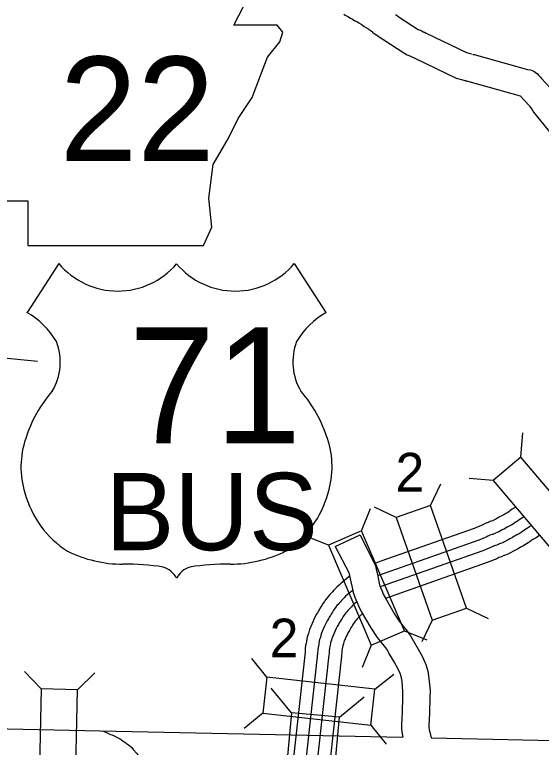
# Model space of a CAD drawing. Extents: x 535214 to 694517, y 381272 to 484355.
# Drawn here: x 541245 to 544123, y 450462 to 454464 of the extents above; entities that cross this region are included whole.
import ezdxf

# ---------------------------------------------------------------- set-up
doc = ezdxf.new("R2010")
doc.units = 0
for name, color, linetype in [('Level 10', 7, 'Continuous'), ('Level 15', 7, 'Continuous'), ('Level 19', 7, 'Continuous'), ('Level 20', 7, 'Continuous'), ('Level 21', 7, 'Continuous'), ('Level 22', 7, 'Continuous')]:
    doc.layers.add(name, color=color, linetype=linetype)

msp = doc.modelspace()

# ---------------------------------------------------------------- linework, layer by layer
at = {"layer": 'Level 10'}
for points in [[(543043.8, 454467.5), (543051.3, 454462.3), (543058.3, 454458.2), (543064.8, 454454.3), (543080.2, 454445.3), (543091.2, 454439.9), (543104.8, 454431.3), (543117.8, 454424.8), (543126.1, 454419.7), (543137.8, 454411.9), (543143.5, 454408.2), (543155, 454400.3), (543167.1, 454392.4), (543174.1, 454388.6), (543176.8, 454386.7), (543187.2, 454378.9), (543195.6, 454373.8), (543198.4, 454371.7), (543201.2, 454369.5), (543209, 454361.9), (543223.9, 454351.5), (543230.3, 454347.8), (543237, 454342.4), (543245.6, 454337.9), (543247.7, 454336.3), (543261.7, 454326.2), (543372.3, 454255.6), (543390.6, 454245.2), (543404.1, 454239.8), (543408.3, 454237.4), (543423.6, 454230.3), (543428, 454228.7), (543431.1, 454227.4), (543658.1, 454117.9), (543700.3, 454105.7), (543709.2, 454103.8)], [(543325.9, 454465.2), (543336.9, 454457), (543346.1, 454450.3), (543449.8, 454384), (543455.6, 454380.7), (543469.2, 454375.4), (543477, 454370.9), (543480.8, 454369.2), (543484.5, 454367.8), (543494.4, 454363.3), (543713.4, 454257.8), (543734.1, 454252.1), (543737.3, 454251.2), (543741.4, 454250.3)], [(543746.1, 454249.1), (543751.1, 454247.6), (543755.7, 454246.3), (544048.3, 454165.2), (544064.2, 454163.4), (544081.3, 454155), (544089.7, 454150.1), (544101.9, 454141.2), (544109.7, 454131.9), (544110.5, 454131), (544118, 454123.7), (544124.4, 454115.6), (544171.2, 454064.1), (544177.7, 454055.6), (544187.3, 454043.2), (544196.4, 454028.9), (544202.3, 454019.9), (544277.6, 453926.2), (544282.3, 453920.1), (544289.2, 453912), (544301, 453903), (544302, 453901.6), (544306.2, 453898.2), (544381.7, 453834.2)], [(543704.5, 454105), (543709.5, 454103.5), (543714.9, 454102), (544007.8, 454020.8), (544056, 453967.8), (544058.7, 453964.4), (544064.3, 453957), (544070.5, 453947.4), (544080.8, 453931.6), (544159.6, 453833.6), (544161.7, 453830.9), (544165.8, 453824.5), (544188.5, 453799.1), (544207.3, 453785.3), (544210.8, 453782.4), (544291, 453714.4)], [(542997, 451560.3), (543132.9, 451623.8)], [(543132.9, 451623.8), (543216.1, 451453.5), (543220.6, 451435.3), (543225.3, 451414.8), (543235, 451367.8), (543239.2, 451350.8), (543244.5, 451335.1), (543252.9, 451314.9), (543259.6, 451298.9), (543270.8, 451277.1), (543319.6, 451193.6), (543346.8, 451151.1), (543366.8, 451126.6), (543390.4, 451096.5), (543408.9, 451071.4), (543422.9, 451045.5), (543450.5, 450998.7), (543474.2, 450957.5), (543492.6, 450914.5), (543503.1, 450877.7), (543507.3, 450852.4), (543509.2, 450837.8), (543514.8, 450773.7), (543514.3, 450734.2), (543512.1, 450648.7), (543508.5, 450581.8), (543508.6, 450572), (543510.4, 450558.7), (543513, 450544.5), (543520.6, 450514.2)], [(542997, 451560.3), (543070.5, 451417.8), (543074.6, 451400.9), (543078.7, 451383), (543088.7, 451334.7), (543095, 451308.9), (543104, 451282.3), (543114.4, 451257.2), (543123.5, 451235.5), (543139.3, 451204.8), (543191.6, 451115.3), (543225.1, 451062.9), (543249.7, 451032.8), (543270.9, 451005.8), (543282, 450990.8), (543292.3, 450971.7), (543320.8, 450923.3), (543339.8, 450890.4), (543351, 450864.1), (543356.6, 450844.6), (543358.9, 450830.8), (543360, 450821.9), (543364.7, 450768.1), (543364.3, 450737.1), (543362.3, 450654.7), (543358.5, 450584.9), (543358.8, 450561.4), (543362.1, 450535.5), (543365.4, 450517.5)], [(541712.2, 450552.7), (543365.4, 450517.5)], [(543520.6, 450514.2), (544358, 450496.3)]]:
    msp.add_lwpolyline(points, dxfattribs=at)
at = {"layer": 'Level 15'}
for points in [[(540958.8, 454767.6), (540924.2, 453475.4), (540903.6, 452646.1), (540863.3, 450747.6), (540863.7, 450746.9), (540866.1, 450744.1), (540868.4, 450741.3), (540881.1, 450730.1), (540887.4, 450723), (540891.4, 450719.5), (540903.1, 450710), (540909.5, 450704.5), (540913.7, 450701.3), (540923.2, 450696.1), (540938.6, 450683.7), (540947.7, 450677.1), (540992.5, 450646.6), (541019.7, 450628.8), (541036.5, 450618.5), (541122.5, 450565.3), (541712.2, 450552.7)], [(541727.5, 450553.1), (541761.4, 450536.2), (541769.5, 450532.8), (541775.4, 450530.3), (541787.8, 450525.6), (541799, 450519.6), (541801.2, 450518.7), (541817.5, 450510.8), (541828, 450503.4), (541838.5, 450496.7), (541851.9, 450487), (541856.5, 450483.2), (541867.6, 450476.4), (541885, 450461.9), (541893.3, 450450.8), (541901.3, 450441.1), (541903.9, 450437.7), (541911.2, 450430.6), (541921.8, 450416.4), (541925.8, 450409.1), (541930.1, 450403), (541995.4, 450287.6)]]:
    msp.add_lwpolyline(points, dxfattribs=at)
at = {"layer": 'Level 19'}
for points in [[(543980.6, 451773), (543964.1, 451762.7), (543951.7, 451753.6), (543946.3, 451749.5), (543940.8, 451745.8), (543936.1, 451742.7), (543929.6, 451739.4), (543917.7, 451733.3), (543906, 451726.6), (543903.1, 451724.8), (543894.2, 451720.6), (543884.1, 451714), (543880.8, 451712.3), (543873.8, 451708.6), (543859.9, 451701), (543859, 451700.5), (543847.1, 451697.4), (543832.5, 451689.9), (543816.1, 451684.5), (543799.4, 451676.4), (543795.1, 451674), (543756.5, 451658.5), (543245.5, 451479), (543210.3, 451465.4)], [(544026.6, 451720.2), (544025.4, 451719.4), (544015.9, 451714), (544002.9, 451705.9), (543992.9, 451698.5), (543986.1, 451693.4), (543978.6, 451688.4), (543970.6, 451683.2), (543961.1, 451678.3), (543950.5, 451672.9), (543940.7, 451667.3), (543935.7, 451664.3), (543927.9, 451660.5), (543919.2, 451654.9), (543913.1, 451651.6), (543906.1, 451648), (543892.2, 451640.3), (543886.1, 451637.2), (543881.4, 451635.3), (543871.8, 451632.8), (543857.9, 451625.6), (543854.4, 451624.7), (543842, 451620.6), (543831, 451615.3), (543824.5, 451611.7), (543780.7, 451594.2), (543228.3, 451400)], [(544064, 451670.1), (544058.2, 451666.2), (544047.9, 451660.3), (544038.1, 451654.2), (544030.3, 451648.4), (544022.2, 451642.3), (544012.9, 451636.1), (544002, 451629.1), (543989.7, 451622.7), (543980.4, 451617.9), (543972.3, 451613.3), (543965.4, 451609.2), (543958.4, 451605.8), (543951.2, 451601.2), (543942.5, 451596.4), (543935.5, 451592.8), (543921.6, 451585.1), (543911.9, 451580.1), (543900.7, 451575.8), (543894.3, 451574.1), (543880.4, 451566.9), (543872.1, 451564.7), (543865.5, 451562.6), (543859.7, 451559.7), (543851.3, 451555.1), (543802.7, 451535.6), (543242.9, 451338.9)], [(544112.2, 451619.8), (544110, 451618.1), (544094.3, 451607.6), (544083.1, 451601.3), (544076.9, 451597.4), (544071.4, 451593.3), (544062, 451586.2), (544050.6, 451578.7), (544036.6, 451569.5), (544021.2, 451561.6), (544013.2, 451557.5), (544007.1, 451554), (543998.1, 451548.6), (543992, 451545.7), (543986.4, 451542.1), (543974.8, 451535.7), (543967.9, 451532.1), (543954, 451524.5), (543940.1, 451517.3), (543921.9, 451510.3), (543919.1, 451509.5), (543905.2, 451502.4), (543891.5, 451498.8), (543891.4, 451498.7), (543891.3, 451498.7), (543880.7, 451492.9), (543826.9, 451471.3), (543271.4, 451276.1)], [(543075.4, 451397.4), (543045.1, 451371.1), (543039.2, 451365.7), (543029.9, 451358.5), (543019.7, 451349.8), (543005.3, 451337.4), (542995.5, 451326.7), (542989.8, 451320.8), (542981.4, 451311.7), (542974.6, 451304.7), (542966.1, 451295.3), (542960.1, 451288.1), (542952.5, 451279.6), (542942.5, 451265.9), (542937.5, 451258.3), (542931.1, 451249.8), (542923.8, 451237.7), (542918.5, 451230.1), (542911.5, 451218), (542904.7, 451207.2), (542899.8, 451197.7), (542893.5, 451187.3), (542889, 451178.4), (542882.4, 451166.8), (542875.7, 451152.2), (542862.7, 451121.6), (542856, 451106.2), (542851.8, 451091.8), (542849.9, 451084.4), (542848.6, 451080.4), (542845.2, 451069.7), (542841.9, 451056.1), (542839.5, 451040.1), (542839.1, 451038), (542837.4, 451030.6), (542835, 451019.2), (542833.4, 451002.4), (542833.1, 450995.9), (542832.4, 450990.1), (542831.6, 450982.3), (542688.9, 449683.3)], [(543092.3, 451320), (543073.3, 451305.2), (543064.3, 451297.6), (543053.4, 451288.1), (543045.6, 451279.5), (543039.7, 451273.5), (543031.4, 451264.4), (543024.8, 451257.7), (543018.1, 451250.3), (543012.2, 451243.1), (543006.1, 451236.3), (542998.9, 451226.5), (542993.6, 451218.6), (542988.2, 451211.4), (542981.6, 451200.3), (542976.5, 451193.1), (542970.3, 451182.4), (542964.5, 451173.1), (542959.9, 451164.3), (542953.6, 451153.7), (542949.5, 451145.8), (542943.7, 451135.5), (542938.6, 451124.4), (542925.9, 451094.5), (542920.8, 451082.7), (542918.1, 451073.7), (542915.9, 451064.9), (542913.8, 451058.8), (542911.4, 451051.3), (542909.5, 451042.9), (542907.4, 451029.6), (542906.7, 451024.8), (542904.5, 451015.6), (542903.1, 451008.9), (542902, 450997.1), (542901.6, 450990.3), (542900.8, 450982.6), (542899.9, 450974.7), (542757.4, 449677.1)], [(543114.1, 451257.8), (543104.9, 451250.1), (543097.1, 451243.3), (543091.1, 451236.7), (543085.1, 451230.5), (543076.7, 451221.4), (543070.4, 451215), (543065.3, 451209.3), (543059.5, 451202.3), (543054.7, 451197), (543050.1, 451190.7), (543044.6, 451182.4), (543040.1, 451176.5), (543034.1, 451166.4), (543029.3, 451159.5), (543023.8, 451150), (543018.8, 451142.1), (543014.6, 451133.9), (543008.2, 451123.2), (543004.5, 451116.1), (542999.5, 451107.2), (542995.8, 451099.2), (542983.3, 451069.8), (542979.7, 451061.4), (542978.5, 451057.3), (542975.9, 451047.1), (542973.2, 451039.1), (542971.7, 451034.6), (542970.8, 451030.9), (542969.2, 451020.1), (542968.1, 451012.8), (542965.5, 451002), (542965, 450999.6), (542964.3, 450992.4), (542963.9, 450985.2), (542962.9, 450975.8), (542962, 450967.7), (542819.7, 449671.4)], [(543145.6, 451194.1), (543135, 451183.3), (543126.7, 451174.2), (543120.6, 451168), (543117.3, 451164.3), (543111.5, 451157.3), (543108.3, 451153.7), (543106.5, 451151.3), (543100.7, 451142.7), (543097.3, 451138), (543091.8, 451129), (543087.3, 451122.5), (543082.6, 451114.4), (543078.6, 451108.1), (543074.7, 451100.4), (543068.2, 451089.7), (543065, 451083.5), (543060.8, 451076), (543058.7, 451071.4), (543046.5, 451042.6), (543044.6, 451038.2), (543041.9, 451027.6), (543038.4, 451017.5), (543038.3, 451016.9), (543037.1, 451009.6), (543035.6, 450999.7), (543033, 450988.9), (543032.9, 450987.2), (543032.4, 450979.5), (543031.3, 450968.4), (543030.3, 450960.1), (542888.1, 449665.1)]]:
    msp.add_lwpolyline(points, dxfattribs=at)
at = {"layer": 'Level 20'}
for p, q in [((544010.6, 452048.1), (544021.4, 452179.7)), ((543859.6, 451920.1), (543728.1, 451930.8)), ((543516.7, 451783.1), (543573.8, 451902.1)), ((543329.9, 451717.4), (543210.9, 451774.5)), ((543141.2, 451644.2), (543190.3, 451766.7)), ((542959.2, 451566.3), (542836.7, 451615.4)), ((543713.6, 451222.7), (543832.6, 451165.6)), ((543526.8, 451157), (543469.7, 451038)), ((543374.9, 451098.1), (543497.4, 451049)), ((543192.8, 451020.2), (543143.7, 450897.7)), ((542623, 450845.3), (542540.4, 450948.2)), ((541390.2, 450781.6), (541298.9, 450876.9)), ((541588.2, 450777.4), (541683.5, 450868.7)), ((543213.4, 450780.4), (543316.4, 450863)), ((542758.3, 450650.6), (542646, 450785.7)), ((543020.7, 450626.4), (543155.8, 450738.7)), ((542601.3, 450648.5), (542498.4, 450565.9)), ((543191.8, 450583.6), (543274.4, 450480.6))]:
    msp.add_line(p, q, dxfattribs=at)
for points in [[(544394.9, 451595.2), (544010.6, 452048.1), (543859.6, 451920.1), (544243.9, 451467.1)], [(543713.6, 451222.7), (543516.7, 451783.1), (543329.9, 451717.4), (543526.8, 451157)], [(543374.9, 451098.1), (543141.2, 451644.2), (542959.2, 451566.3), (543192.8, 451020.2)], [(543213.4, 450780.4), (542623, 450845.3), (542601.3, 450648.5), (543191.8, 450583.6)], [(541390.2, 450781.6), (541377.6, 450187.8), (541575.5, 450183.6), (541588.2, 450777.4)], [(542758.3, 450650.6), (542717.9, 450218.9), (542980.3, 450194.7), (543020.7, 450626.4)]]:
    msp.add_lwpolyline(points, close=True, dxfattribs=at)
at = {"layer": 'Level 21'}
msp.add_line((540825.4, 452626.7), (541369.3, 452572.6), dxfattribs=at)
msp.add_lwpolyline([(541103.5, 454635.2), (541172.1, 454178.5), (541141.6, 453485.7), (541202.5, 453447.6), (541316.7, 453447.6), (541316.7, 453204), (542276, 453204), (542321.6, 453303), (542306.4, 453462.8), (542329.2, 453645.5), (542413, 453790.2), (542466.3, 453896.8), (542542.4, 454011), (542588.1, 454132.8), (542626.2, 454231.7), (542694.7, 454315.5), (542709.9, 454368.8), (542679.4, 454406.8), (542443.4, 454406.8), (542496.7, 454513.4), (542504.3, 454581.9), (542472.8, 454634.6)], close=True, dxfattribs=at)
at = {"layer": 'Level 22'}
for p, q in [((541486.1, 453104.6), (541313, 452836.9)), ((542773, 453104.6), (542946.1, 452836.9))]:
    msp.add_line(p, q, dxfattribs=at)
for centre, radius, start, end in [((541808.4, 453375.8), 421.2, 220.075, 319.6701), ((542450.7, 453375.8), 421.2, 220.3299, 319.925), ((541086.9, 452448.3), 449.7, 30.7809, 59.9883), ((543172.3, 452448.3), 449.7, 120.0117, 149.2191), ((541185.8, 452566.9), 308.3, 328.8105, 21.2108), ((543073.3, 452566.9), 308.3, 158.7892, 211.1895), ((541991.9, 451935), 719.2, 138.9565, 162.6913), ((542267.2, 451935), 719.2, 17.3087, 41.0435), ((541754.5, 451994), 475.2, 160.9576, 197.3819), ((542504.6, 451994), 475.2, 342.6181, 19.0424), ((541831.9, 451995.3), 549.8, 195.1074, 237.1312), ((542427.3, 451995.3), 549.8, 302.8688, 344.8926), ((541842.1, 452168.5), 706, 244.0771, 269.5779), ((542417, 452168.5), 706, 270.4221, 295.9229), ((541858.5, 450169.3), 1293.3, 81.1942, 90.9539), ((542400.7, 450169.3), 1293.3, 89.0461, 98.8058), ((542020.2, 451328.9), 123.9, 28.0342, 72.9864), ((542239, 451328.9), 123.9, 107.0136, 151.9658)]:
    msp.add_arc(centre, radius, start, end, dxfattribs=at)

# ---------------------------------------------------------------- texts
at = {"layer": 'Level 20'}
for p in [(543326.3, 451859.8), (542638.5, 450954.2)]:
    msp.add_text('2', height=211.2, dxfattribs=at).set_placement(p)
at = {"layer": 'Level 21'}
msp.add_text('22', height=570.24, dxfattribs=at).set_placement((541490.4, 453664.8))
at = {"layer": 'Level 22'}
for s, height, p in [('71', 633.6, (541868.6, 452122.3)), ('BUS', 422.4, (541740.8, 451539.3))]:
    msp.add_text(s, height=height, dxfattribs=at).set_placement(p)

doc.saveas('drawing.dxf')
